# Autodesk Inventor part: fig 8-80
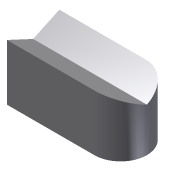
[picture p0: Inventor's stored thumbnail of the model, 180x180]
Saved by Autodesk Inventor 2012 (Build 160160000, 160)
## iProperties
Created: 2011-07
Part Number: fig 8-80
Material: Default
Document SubType Name: Modeling
Designer: CadCim
Density: 1 g/cm^3
Author: CadCim
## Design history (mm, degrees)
sketch "Sketch1"
  geometry: L1 (-16, 5)-(-16, -7); L2 (-16, -7)-(4, -7); L3 (4, 5)-(-16, 5); A1 r 6 centre (4, -1) between (4, -7) and (4, 5); 1 further point
  constraints: 6 end point, 2 point on circle, 2 tangent, 1 centre point, 1 parallel, 1 perpendicular, 1 vertical
extrude "Extrusion1" new body sketch "Sketch1" distance "d0" = 10; taper "d1" = 0 deg
sketch "Sketch2"
  geometry: L1 (-16, -1)-(10, -1); 1 further point
  constraints: 2 end point, 1 horizontal
feature "FaceDraft1" sketch "Sketch2" dims angle "d2" = -25 deg
body "Solid1"
